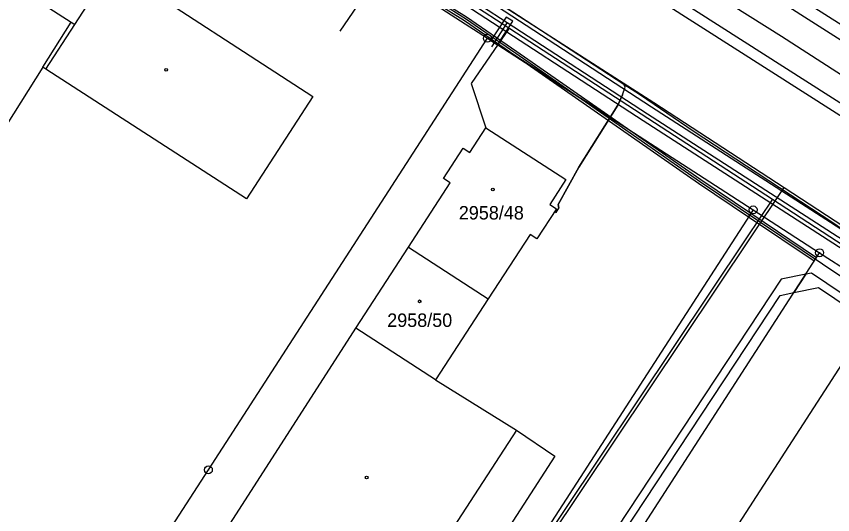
# Model space of a CAD drawing. Extents: x -621168 to -620292, y -1122748 to -1122069.
# Drawn here: x -620762.3 to -620659.1, y -1122523.2 to -1122460.2 of the extents above; entities that cross this region are included whole.
import ezdxf

# ---------------------------------------------------------------- set-up
doc = ezdxf.new("R2010")
doc.units = 0
for name, color, linetype in [('CETIN', 7, 'Continuous'), ('GasNet', 7, 'Continuous'), ('HranDP', 7, 'Continuous'), ('Hranice parcel', 7, 'Continuous'), ('itself', 7, 'Continuous'), ('Parcelní čísla', 7, 'Continuous'), ('SEE', 7, 'Continuous'), ('VAS stoka', 7, 'Continuous'), ('VAS vodovod', 7, 'Continuous'), ('Vnitřní kresba', 7, 'Continuous'), ('Věcná břemena k části', 7, 'Continuous'), ('Značky bodu BP', 7, 'Continuous'), ('Značky budov', 7, 'Continuous')]:
    doc.layers.add(name, color=color, linetype=linetype)

msp = doc.modelspace()

# ---------------------------------------------------------------- linework, layer by layer
at = {"layer": 'CETIN'}
for points in [[(-620721.34, -1122462.04), (-620716.98, -1122455.59), (-620713.88, -1122450.37)], [(-620713.88, -1122450.37), (-620713.18, -1122450.73), (-620698.82, -1122460.09), (-620685.49, -1122468.76)], [(-620694.25, -1122484.84), (-620694.04, -1122484.98), (-620693.69, -1122484.45), (-620693.79, -1122484), (-620691.17, -1122479.25), (-620686.25, -1122471.41), (-620685.67, -1122470.12), (-620685.31, -1122469.14), (-620685.49, -1122468.76)], [(-620685.49, -1122468.76), (-620683.38, -1122470.13), (-620676.74, -1122474.66), (-620659.07, -1122486.24), (-620646.43, -1122495.05)], [(-620685.67, -1122470.12), (-620686.25, -1122471.41), (-620691.17, -1122479.25), (-620693.79, -1122484), (-620693.69, -1122484.45)]]:
    msp.add_lwpolyline(points, dxfattribs=at)
at = {"layer": 'GasNet'}
for points in [[(-620782.63, -1122409.86), (-620782.01, -1122410.24), (-620780.25, -1122411.07), (-620777.02, -1122412.94), (-620768.84, -1122416.49), (-620765.93, -1122417.88), (-620758.63, -1122422.59), (-620737.62, -1122436.24), (-620727.26, -1122442.97), (-620706.73, -1122456.7), (-620700.22, -1122460.96), (-620682.51, -1122472.52), (-620658.5, -1122488), (-620649.67, -1122493.31), (-620649.45, -1122493.45), (-620648.52, -1122494.04), (-620647.09, -1122494.92), (-620646.9, -1122495.04), (-620639.06, -1122500.54), (-620610.88, -1122519.2), (-620586.31, -1122535.34), (-620573.22, -1122543.96)], [(-620700.22, -1122460.96), (-620702.23, -1122464.06)]]:
    msp.add_lwpolyline(points, dxfattribs=at)
at = {"layer": 'HranDP'}
msp.add_lwpolyline([(-620821.12, -1122358.76), (-620741.46, -1122408.09), (-620679.51, -1122447.56), (-620545.92, -1122532.26), (-620521.41, -1122548.27), (-620511.29, -1122557.64)], dxfattribs=at)
at = {"layer": 'Hranice parcel'}
for p, q in [((-620757.34, -1122427.68), (-620702.74, -1122462.95)), ((-620702.74, -1122462.95), (-620669.14, -1122484.66)), ((-620669.14, -1122484.66), (-620660.74, -1122490.09)), ((-620712.73, -1122489.39), (-620702.63, -1122495.93)), ((-620722.11, -1122585.09), (-620660.74, -1122490.09)), ((-620660.74, -1122490.09), (-620576.58, -1122544.45))]:
    msp.add_line(p, q, dxfattribs=at)
for points in [[(-620821.12, -1122358.76), (-620741.46, -1122408.09), (-620679.51, -1122447.56), (-620545.92, -1122532.26), (-620521.41, -1122548.27), (-620511.29, -1122557.64)], [(-620821.12, -1122358.76), (-620807.67, -1122367.84), (-620645.72, -1122471.03), (-620587.17, -1122509.18), (-620511.29, -1122557.64)], [(-620557.45, -1122536.96), (-620684.91, -1122455.63), (-620825.92, -1122365.89)], [(-620758.93, -1122466.63), (-620763.57, -1122474.01), (-620789, -1122457.71), (-620780.78, -1122444.6), (-620755.36, -1122460.94), (-620754.9, -1122461.23), (-620750.13, -1122453.84), (-620724.79, -1122470.34), (-620733.19, -1122483.27), (-620758.55, -1122466.88), (-620758.93, -1122466.63)], [(-620757.37, -1122547.51), (-620738.01, -1122517.55), (-620702.74, -1122462.95)], [(-620712.73, -1122489.39), (-620707.44, -1122481.23), (-620708.28, -1122480.69), (-620705.81, -1122476.87), (-620704.97, -1122477.41), (-620702.93, -1122474.27), (-620692.81, -1122480.83), (-620694.86, -1122483.99), (-620694.01, -1122484.54), (-620696.48, -1122488.34), (-620697.33, -1122487.79), (-620702.63, -1122495.93)], [(-620669.14, -1122484.66), (-620704.41, -1122539.26), (-620723.81, -1122569.32)], [(-620702.63, -1122495.93), (-620709.28, -1122506.15), (-620699.07, -1122512.52), (-620694.2, -1122515.81), (-620710.42, -1122540.95), (-620717.32, -1122551.67), (-620742.46, -1122535.43), (-620735.6, -1122524.88), (-620719.36, -1122499.62), (-620712.73, -1122489.39)], [(-620581.67, -1122552.32), (-620657.43, -1122503.38), (-620713.46, -1122590.12)]]:
    msp.add_lwpolyline(points, dxfattribs=at)
at = {"layer": 'itself'}
msp.add_lwpolyline([(-620570.67, -1122549.95), (-620584.48, -1122540.56), (-620609.76, -1122524.78), (-620613.13, -1122522.62), (-620616.25, -1122520.59), (-620644.13, -1122502.42), (-620648.74, -1122499.33), (-620649.95, -1122498.54), (-620675.91, -1122481.07), (-620699.14, -1122464.9), (-620705.51, -1122460.51), (-620711.67, -1122456.57), (-620715.75, -1122454.11), (-620716.79, -1122453.45), (-620721.67, -1122450.84), (-620745.77, -1122435.49), (-620776.46, -1122415.3)], dxfattribs=at)
at = {"layer": 'SEE'}
msp.add_lwpolyline([(-620377.19, -1122637.27), (-620390.25, -1122629.02), (-620411.93, -1122614.96), (-620423.13, -1122608.01), (-620468.34, -1122579.91), (-620468.34, -1122579.91), (-620460.94, -1122568.1), (-620517.42, -1122533.03), (-620535, -1122522.48), (-620545.41, -1122539.45), (-620611.37, -1122497.7), (-620665.57, -1122462.75), (-620686.03, -1122449.83), (-620727.54, -1122423.18), (-620794.51, -1122379.86), (-620815.52, -1122356.95), (-620832.17, -1122344.66), (-620847.81, -1122332.59), (-620908.26, -1122294.69)], dxfattribs=at)
at = {"layer": 'VAS stoka'}
for points in [[(-620781.72, -1122408.87), (-620776.69, -1122412.14), (-620774.2, -1122412.02), (-620772.21, -1122412.95), (-620766.77, -1122415.95), (-620758.11, -1122421.89), (-620737.16, -1122435.39), (-620726.71, -1122442.22), (-620705.9, -1122455.54), (-620681.71, -1122471.08), (-620665.23, -1122481.83), (-620655.61, -1122488.12), (-620638.12, -1122499.53), (-620609.99, -1122517.38), (-620585.88, -1122533.44), (-620564.23, -1122548.6), (-620546.83, -1122572.05), (-620541.25, -1122582.33), (-620541.87, -1122584.42), (-620543.53, -1122584.85), (-620544.25, -1122585.03)], [(-620730.84, -1122580.01), (-620699.26, -1122532.75), (-620665.23, -1122481.83)]]:
    msp.add_lwpolyline(points, dxfattribs=at)
at = {"layer": 'VAS vodovod'}
for points in [[(-620783.05, -1122410.36), (-620779.49, -1122412.44), (-620776.82, -1122413.57), (-620766.15, -1122419), (-620759.23, -1122423.16), (-620738.05, -1122436.88), (-620666.7, -1122483.31), (-620630.69, -1122506.76), (-620611.44, -1122519.95), (-620587.32, -1122536.52), (-620566.14, -1122551.51), (-620558.22, -1122559.71), (-620551.85, -1122569.08), (-620547.83, -1122576.32), (-620546.15, -1122586.98), (-620546.1, -1122587.26)], [(-620699.97, -1122461.66), (-620704.79, -1122468.67), (-620702.93, -1122474.27)], [(-620666.7, -1122483.31), (-620668.33, -1122485.75), (-620669.96, -1122488.2), (-620702.2, -1122536.43), (-620731.18, -1122579.81)]]:
    msp.add_lwpolyline(points, dxfattribs=at)
at = {"layer": 'Vnitřní kresba'}
for p, q in [((-620810.36, -1122373.73), (-620648.08, -1122477.56)), ((-620758.93, -1122466.63), (-620755.36, -1122460.94)), ((-620758.55, -1122466.88), (-620754.9, -1122461.23)), ((-620709.28, -1122506.15), (-620719.36, -1122499.62)), ((-620699.07, -1122512.52), (-620715.48, -1122537.82))]:
    msp.add_line(p, q, dxfattribs=at)
at = {"layer": 'Věcná břemena k části'}
for points in [[(-620572.64, -1122543.14), (-620585.76, -1122534.5), (-620610.33, -1122518.37), (-620638.51, -1122499.7), (-620681.97, -1122471.68), (-620706.18, -1122455.87), (-620726.71, -1122442.14), (-620758.09, -1122421.75), (-620765.44, -1122417.01)], [(-620766.42, -1122418.75), (-620759.17, -1122423.43), (-620727.81, -1122443.8), (-620707.28, -1122457.53), (-620683.05, -1122473.36), (-620639.61, -1122501.38), (-620611.43, -1122520.03), (-620586.86, -1122536.18), (-620573.8, -1122544.78)], [(-620724.09, -1122583.94), (-620665.73, -1122495.48), (-620663.99, -1122495.13), (-620662.49, -1122492.8), (-620665.58, -1122493.44), (-620724.96, -1122583.43)]]:
    msp.add_lwpolyline(points, dxfattribs=at)
for points in [[(-620685.56, -1122474.05), (-620699, -1122464.69), (-620705.37, -1122460.3), (-620715.62, -1122453.89), (-620721.54, -1122450.62), (-620741.38, -1122437.99), (-620715.88, -1122454.33), (-620705.65, -1122460.72), (-620699.28, -1122465.11)], [(-620701.45, -1122463.78), (-620699.53, -1122460.81), (-620700.37, -1122460.27), (-620702.29, -1122463.24)], [(-620669.44, -1122485.12), (-620675.77, -1122480.86), (-620685.56, -1122474.05), (-620697.72, -1122466.19), (-620676.05, -1122481.28), (-620669.71, -1122485.55)], [(-620669.44, -1122485.12), (-620669.71, -1122485.55), (-620661.41, -1122491.13), (-620661.14, -1122490.71)], [(-620662.49, -1122492.8), (-620663.99, -1122495.13), (-620660.86, -1122494.48), (-620566.61, -1122558.04), (-620561.72, -1122564.46), (-620556.24, -1122574.37), (-620550.21, -1122590.27), (-620556.49, -1122571.86), (-620560.88, -1122563.9), (-620565.91, -1122557.3), (-620661.78, -1122492.65)]]:
    msp.add_lwpolyline(points, close=True, dxfattribs=at)
at = {"layer": 'Značky bodu BP'}
for centre, radius in [((-620702.74, -1122462.95), 0.5), ((-620702.74, -1122462.95), 0.0303), ((-620669.14, -1122484.66), 0.5), ((-620669.14, -1122484.66), 0.0303), ((-620660.74, -1122490.09), 0.5), ((-620660.74, -1122490.09), 0.0303), ((-620738.01, -1122517.55), 0.5), ((-620738.01, -1122517.55), 0.0303)]:
    msp.add_circle(centre, radius, dxfattribs=at)
at = {"layer": 'Značky budov'}
for centre in [(-620743.35, -1122466.95), (-620702.06, -1122482.08), (-620711.3, -1122496.23), (-620718, -1122518.52)]:
    msp.add_circle(centre, 0.175, dxfattribs=at)

# ---------------------------------------------------------------- texts
at = {"layer": 'Parcelní čísla'}
for s, p in [('2958/48', (-620706.35, -1122485.88)), ('2958/50', (-620715.4, -1122499.47))]:
    msp.add_text(s, height=1.7, dxfattribs=at).set_placement(p)

doc.saveas('drawing.dxf')
